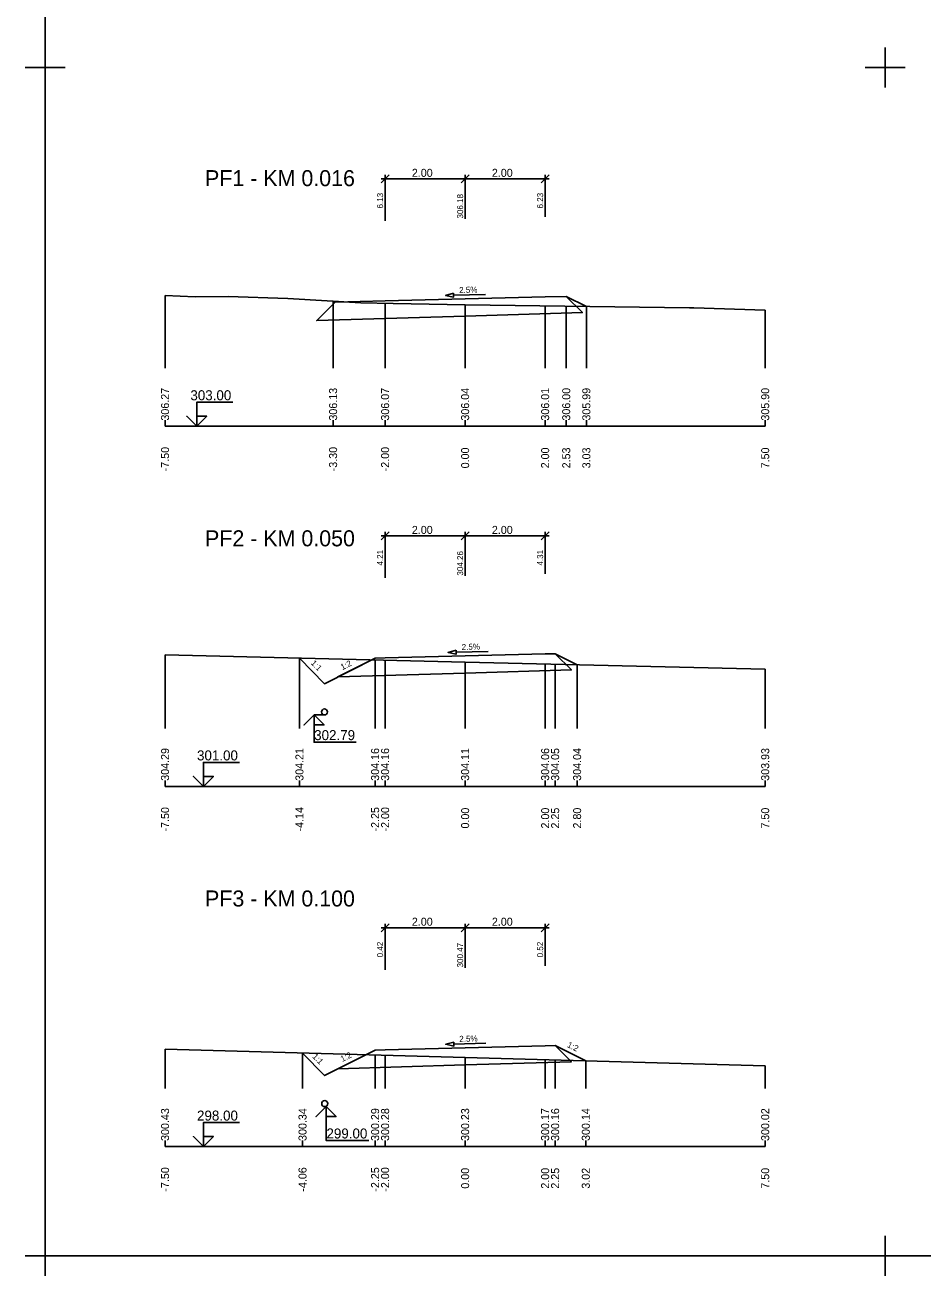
# Model space of a CAD drawing. Extents: x -5 to 1895, y -2 to 602.
# Drawn here: x -5 to 219.4, y -2.3 to 310.3 of the extents above; entities that cross this region are included whole.
import ezdxf

# ---------------------------------------------------------------- set-up
doc = ezdxf.new("R2010")
doc.units = 0
for name, color, linetype in [('KOTA', 7, 'Continuous'), ('KOTA_DELKY', 7, 'Continuous'), ('KOTA_DELKY_CONT', 7, 'Continuous'), ('KRIZENI', 7, 'Continuous'), ('NS_TELESO_VOZOVKY', 7, 'Continuous'), ('NS_V_PF', 7, 'Continuous'), ('REZY_PF_PUVODNI', 7, 'Continuous'), ('SESTAVY_REZU_PF', 7, 'Continuous'), ('SKLON', 7, 'Continuous'), ('SVK', 7, 'Continuous')]:
    doc.layers.add(name, color=color, linetype=linetype)

msp = doc.modelspace()

# ---------------------------------------------------------------- linework, layer by layer
for p, q in [((0, 304.67), (0, 294.67)), ((0, 304.67), (0, 294.67)), ((0, 304.67), (0, 294.67)), ((0, 304.67), (0, 294.67)), ((0, 304.67), (0, 294.67)), ((0, 304.67), (0, 294.67)), ((0, 304.67), (0, 294.67)), ((0, 304.67), (0, 294.67)), ((0, 304.67), (0, 294.67)), ((0, 304.67), (0, 294.67)), ((0, 304.67), (0, 294.67)), ((0, 304.67), (0, 294.67)), ((0, 304.67), (0, 294.67)), ((0, 304.67), (0, 294.67)), ((0, 304.67), (0, 294.67)), ((0, 304.67), (0, 294.67)), ((0, 304.67), (0, 294.67)), ((0, 304.67), (0, 294.67)), ((0, 304.67), (0, 294.67)), ((0, 304.67), (0, 294.67)), ((0, 304.67), (0, 294.67)), ((0, 304.67), (0, 294.67)), ((0, 304.67), (0, 294.67)), ((0, 304.67), (0, 294.67)), ((0, 304.67), (0, 294.67)), ((0, 304.67), (0, 294.67)), ((0, 304.67), (0, 294.67)), ((0, 304.67), (0, 294.67)), ((0, 304.67), (0, 294.67)), ((0, 304.67), (0, 294.67)), ((0, 304.67), (0, 294.67)), ((0, 304.67), (0, 294.67)), ((0, 304.67), (0, 294.67)), ((0, 304.67), (0, 294.67)), ((0, 304.67), (0, 294.67)), ((0, 304.67), (0, 294.67)), ((210, 304.67), (210, 294.67)), ((210, 304.67), (210, 294.67)), ((210, 304.67), (210, 294.67)), ((210, 304.67), (210, 294.67)), ((210, 304.67), (210, 294.67)), ((210, 304.67), (210, 294.67)), ((210, 304.67), (210, 294.67)), ((210, 304.67), (210, 294.67)), ((210, 304.67), (210, 294.67)), ((210, 304.67), (210, 294.67)), ((210, 304.67), (210, 294.67)), ((210, 304.67), (210, 294.67)), ((210, 304.67), (210, 294.67)), ((210, 304.67), (210, 294.67)), ((210, 304.67), (210, 294.67)), ((210, 304.67), (210, 294.67)), ((210, 304.67), (210, 294.67)), ((210, 304.67), (210, 294.67)), ((210, 304.67), (210, 294.67)), ((210, 304.67), (210, 294.67)), ((210, 304.67), (210, 294.67)), ((210, 304.67), (210, 294.67)), ((210, 304.67), (210, 294.67)), ((210, 304.67), (210, 294.67)), ((210, 304.67), (210, 294.67)), ((210, 304.67), (210, 294.67)), ((210, 304.67), (210, 294.67)), ((210, 304.67), (210, 294.67)), ((210, 304.67), (210, 294.67)), ((210, 304.67), (210, 294.67)), ((210, 304.67), (210, 294.67)), ((210, 304.67), (210, 294.67)), ((210, 304.67), (210, 294.67)), ((210, 304.67), (210, 294.67)), ((210, 304.67), (210, 294.67)), ((210, 304.67), (210, 294.67)), ((210, 304.67), (210, 294.67)), ((210, 304.67), (210, 294.67)), ((210, 304.67), (210, 294.67)), ((210, 304.67), (210, 294.67)), ((210, 304.67), (210, 294.67)), ((210, 304.67), (210, 294.67)), ((210, 304.67), (210, 294.67)), ((210, 304.67), (210, 294.67)), ((210, 304.67), (210, 294.67)), ((210, 304.67), (210, 294.67)), ((210, 304.67), (210, 294.67)), ((210, 304.67), (210, 294.67)), ((210, 304.67), (210, 294.67)), ((210, 304.67), (210, 294.67)), ((210, 304.67), (210, 294.67)), ((210, 304.67), (210, 294.67)), ((210, 304.67), (210, 294.67)), ((210, 304.67), (210, 294.67)), ((5, 299.67), (-5, 299.67)), ((5, 299.67), (-5, 299.67)), ((5, 299.67), (-5, 299.67)), ((5, 299.67), (-5, 299.67)), ((5, 299.67), (-5, 299.67)), ((5, 299.67), (-5, 299.67)), ((5, 299.67), (-5, 299.67)), ((5, 299.67), (-5, 299.67)), ((5, 299.67), (-5, 299.67)), ((5, 299.67), (-5, 299.67)), ((5, 299.67), (-5, 299.67)), ((5, 299.67), (-5, 299.67)), ((5, 299.67), (-5, 299.67)), ((5, 299.67), (-5, 299.67)), ((5, 299.67), (-5, 299.67)), ((5, 299.67), (-5, 299.67)), ((5, 299.67), (-5, 299.67)), ((5, 299.67), (-5, 299.67)), ((5, 299.67), (-5, 299.67)), ((5, 299.67), (-5, 299.67)), ((5, 299.67), (-5, 299.67)), ((5, 299.67), (-5, 299.67)), ((5, 299.67), (-5, 299.67)), ((5, 299.67), (-5, 299.67)), ((5, 299.67), (-5, 299.67)), ((5, 299.67), (-5, 299.67)), ((5, 299.67), (-5, 299.67)), ((5, 299.67), (-5, 299.67)), ((5, 299.67), (-5, 299.67)), ((5, 299.67), (-5, 299.67)), ((5, 299.67), (-5, 299.67)), ((5, 299.67), (-5, 299.67)), ((5, 299.67), (-5, 299.67)), ((5, 299.67), (-5, 299.67)), ((5, 299.67), (-5, 299.67)), ((5, 299.67), (-5, 299.67)), ((215, 299.67), (205, 299.67)), ((215, 299.67), (205, 299.67)), ((215, 299.67), (205, 299.67)), ((215, 299.67), (205, 299.67)), ((215, 299.67), (205, 299.67)), ((215, 299.67), (205, 299.67)), ((215, 299.67), (205, 299.67)), ((215, 299.67), (205, 299.67)), ((215, 299.67), (205, 299.67)), ((215, 299.67), (205, 299.67)), ((215, 299.67), (205, 299.67)), ((215, 299.67), (205, 299.67)), ((215, 299.67), (205, 299.67)), ((215, 299.67), (205, 299.67)), ((215, 299.67), (205, 299.67)), ((215, 299.67), (205, 299.67)), ((215, 299.67), (205, 299.67)), ((215, 299.67), (205, 299.67)), ((215, 299.67), (205, 299.67)), ((215, 299.67), (205, 299.67)), ((215, 299.67), (205, 299.67)), ((215, 299.67), (205, 299.67)), ((215, 299.67), (205, 299.67)), ((215, 299.67), (205, 299.67)), ((215, 299.67), (205, 299.67)), ((215, 299.67), (205, 299.67)), ((215, 299.67), (205, 299.67)), ((215, 299.67), (205, 299.67)), ((215, 299.67), (205, 299.67)), ((215, 299.67), (205, 299.67)), ((215, 299.67), (205, 299.67)), ((215, 299.67), (205, 299.67)), ((215, 299.67), (205, 299.67)), ((215, 299.67), (205, 299.67)), ((215, 299.67), (205, 299.67)), ((215, 299.67), (205, 299.67)), ((215, 299.67), (205, 299.67)), ((215, 299.67), (205, 299.67)), ((215, 299.67), (205, 299.67)), ((215, 299.67), (205, 299.67)), ((215, 299.67), (205, 299.67)), ((215, 299.67), (205, 299.67)), ((215, 299.67), (205, 299.67)), ((215, 299.67), (205, 299.67)), ((215, 299.67), (205, 299.67)), ((215, 299.67), (205, 299.67)), ((215, 299.67), (205, 299.67)), ((215, 299.67), (205, 299.67)), ((215, 299.67), (205, 299.67)), ((215, 299.67), (205, 299.67)), ((215, 299.67), (205, 299.67)), ((215, 299.67), (205, 299.67)), ((215, 299.67), (205, 299.67)), ((215, 299.67), (205, 299.67)), ((0, 7.67), (0, -2.33)), ((0, 7.67), (0, -2.33)), ((0, 7.67), (0, -2.33)), ((0, 7.67), (0, -2.33)), ((0, 7.67), (0, -2.33)), ((0, 7.67), (0, -2.33)), ((0, 7.67), (0, -2.33)), ((0, 7.67), (0, -2.33)), ((210, 7.67), (210, -2.33)), ((210, 7.67), (210, -2.33)), ((210, 7.67), (210, -2.33)), ((210, 7.67), (210, -2.33)), ((210, 7.67), (210, -2.33)), ((210, 7.67), (210, -2.33)), ((210, 7.67), (210, -2.33)), ((210, 7.67), (210, -2.33)), ((210, 7.67), (210, -2.33)), ((210, 7.67), (210, -2.33)), ((210, 7.67), (210, -2.33)), ((210, 7.67), (210, -2.33)), ((5, 2.67), (-5, 2.67)), ((5, 2.67), (-5, 2.67)), ((5, 2.67), (-5, 2.67)), ((5, 2.67), (-5, 2.67)), ((5, 2.67), (-5, 2.67)), ((5, 2.67), (-5, 2.67)), ((5, 2.67), (-5, 2.67)), ((5, 2.67), (-5, 2.67)), ((215, 2.67), (205, 2.67)), ((215, 2.67), (205, 2.67)), ((215, 2.67), (205, 2.67)), ((215, 2.67), (205, 2.67)), ((215, 2.67), (205, 2.67)), ((215, 2.67), (205, 2.67)), ((215, 2.67), (205, 2.67)), ((215, 2.67), (205, 2.67)), ((215, 2.67), (205, 2.67)), ((215, 2.67), (205, 2.67)), ((215, 2.67), (205, 2.67)), ((215, 2.67), (205, 2.67))]:
    msp.add_line(p, q)
msp.add_lwpolyline([(0, 596.67), (1890, 596.67), (1890, 2.67), (0, 2.67)], close=True)
at = {"layer": 'KOTA'}
for points in [[(37.91, 210), (35.41, 212.5), (37.91, 210), (37.91, 216), (46.91, 216)], [(37.91, 210), (40.41, 212.5), (37.91, 212.5), (37.91, 210)], [(37.91, 210), (40.41, 212.5), (37.91, 212.5)], [(67.25, 137.86), (64.75, 135.36), (67.25, 137.86), (67.25, 131.04), (77.79, 131.04)], [(69.85, 137.86), (67.25, 137.86)], [(67.25, 137.86), (69.75, 135.36), (67.25, 135.36), (67.25, 137.86)], [(67.25, 137.86), (69.75, 135.36), (67.25, 135.36)], [(39.57, 120), (37.07, 122.5), (39.57, 120), (39.57, 126), (48.57, 126)], [(39.57, 120), (42.07, 122.5), (39.57, 122.5), (39.57, 120)], [(39.57, 120), (42.07, 122.5), (39.57, 122.5)], [(70.25, 39.98), (67.75, 37.48), (70.25, 39.98), (70.25, 31.53), (80.93, 31.53)], [(69.91, 39.98), (70.25, 39.98)], [(70.25, 39.98), (72.75, 37.48), (70.25, 37.48), (70.25, 39.98)], [(70.25, 39.98), (72.75, 37.48), (70.25, 37.48)], [(39.57, 30), (37.07, 32.5), (39.57, 30), (39.57, 36), (48.57, 36)], [(39.57, 30), (42.07, 32.5), (39.57, 32.5), (39.57, 30)], [(39.57, 30), (42.07, 32.5), (39.57, 32.5)]]:
    msp.add_lwpolyline(points, dxfattribs=at)
at = {"layer": 'KOTA_DELKY'}
for points in [[(84, 270.83), (86, 272.83)], [(85, 261.33), (85, 272.83)], [(104, 270.83), (106, 272.83)], [(104, 270.83), (106, 272.83)], [(105, 261.83), (105, 272.83)], [(105, 261.83), (105, 272.83)], [(124, 270.83), (126, 272.83)], [(125, 262.33), (125, 272.83)], [(84, 271.83), (106, 271.83)], [(104, 271.83), (126, 271.83)], [(84, 181.6), (86, 183.6)], [(84, 182.6), (106, 182.6)], [(85, 172.1), (85, 183.6)], [(104, 181.6), (106, 183.6)], [(104, 181.6), (106, 183.6)], [(104, 182.6), (126, 182.6)], [(105, 172.6), (105, 183.6)], [(105, 172.6), (105, 183.6)], [(124, 181.6), (126, 183.6)], [(125, 173.1), (125, 183.6)], [(84, 83.69), (86, 85.69)], [(84, 83.69), (86, 85.69)], [(84, 84.69), (106, 84.69)], [(84, 84.69), (106, 84.69)], [(85, 74.19), (85, 85.69)], [(85, 74.19), (85, 85.69)], [(104, 83.69), (106, 85.69)], [(104, 83.69), (106, 85.69)], [(104, 83.69), (106, 85.69)], [(104, 83.69), (106, 85.69)], [(104, 84.69), (126, 84.69)], [(104, 84.69), (126, 84.69)], [(105, 74.69), (105, 85.69)], [(105, 74.69), (105, 85.69)], [(105, 74.69), (105, 85.69)], [(105, 74.69), (105, 85.69)], [(124, 83.69), (126, 85.69)], [(124, 83.69), (126, 85.69)], [(125, 75.19), (125, 85.69)], [(125, 75.19), (125, 85.69)]]:
    msp.add_lwpolyline(points, dxfattribs=at)
at = {"layer": 'KRIZENI'}
for centre in [(69.85, 138.61), (69.91, 40.73)]:
    msp.add_circle(centre, 0.75, dxfattribs=at)
at = {"layer": 'NS_TELESO_VOZOVKY'}
for points in [[(105, 241.83), (125, 242.33), (130.27, 242.46), (134.33, 238.41), (105, 237.53), (67.9, 236.42), (72.5, 241.02), (85, 241.33), (105, 241.83)], [(105, 152.6), (125, 153.1), (127.5, 153.16), (131.57, 149.1), (105, 148.3), (73.2, 147.35), (82.5, 152.04), (85, 152.1), (105, 152.6)], [(105, 54.69), (125, 55.19), (127.5, 55.25), (131.57, 51.19), (105, 50.39), (73.2, 49.44), (82.5, 54.13), (85, 54.19), (105, 54.69)], [(105, 54.69), (125, 55.19), (127.5, 55.25), (131.57, 51.19), (105, 50.39), (73.2, 49.44), (82.5, 54.13), (85, 54.19), (105, 54.69)]]:
    msp.add_lwpolyline(points, dxfattribs=at)
at = {"layer": 'NS_V_PF'}
for points in [[(72, 241.27), (72.5, 241.02), (85, 241.33), (105, 241.83), (125, 242.33), (130.27, 242.46), (135.3, 239.95)], [(63.59, 152.07), (69.87, 145.66), (82.5, 152.04), (85, 152.1), (105, 152.6), (125, 153.1), (127.5, 153.16), (132.99, 150.41)], [(64.36, 53.38), (69.87, 47.76), (82.5, 54.13), (85, 54.19), (105, 54.69), (125, 55.19), (127.5, 55.25), (135.16, 51.42)], [(64.36, 53.38), (69.87, 47.76), (82.5, 54.13), (85, 54.19), (105, 54.69), (125, 55.19), (127.5, 55.25), (135.16, 51.42)]]:
    msp.add_lwpolyline(points, dxfattribs=at)
at = {"layer": 'REZY_PF_PUVODNI'}
for points in [[(30, 242.68), (37.51, 242.32), (45.81, 242.45), (60.66, 241.93), (78.9, 240.87), (87, 240.64), (105, 240.38), (161.04, 239.58), (162.2, 239.58), (180, 239.02)], [(30, 152.87), (105, 151.08), (105, 151.08), (180, 149.29)], [(30, 54.33), (105, 52.26), (105, 52.26), (180, 50.19)]]:
    msp.add_lwpolyline(points, dxfattribs=at)
at = {"layer": 'SESTAVY_REZU_PF'}
for points in [[(30, 210), (180, 210)], [(30, 120), (180, 120)], [(30, 30), (180, 30)]]:
    msp.add_lwpolyline(points, dxfattribs=at)
at = {"layer": 'SKLON'}
for points in [[(102.11, 243.26), (100.12, 242.71), (102.13, 242.26), (102.11, 243.26)], [(102.12, 242.76), (110.12, 242.96)], [(102.74, 154.04), (100.75, 153.49), (102.76, 153.04), (102.74, 154.04)], [(102.75, 153.54), (110.75, 153.74)], [(102.15, 56.12), (100.17, 55.57), (102.18, 55.12), (102.15, 56.12)], [(102.17, 55.62), (110.16, 55.82)]]:
    msp.add_lwpolyline(points, dxfattribs=at)
for points in [[(102.11, 243.26), (100.12, 242.71), (102.13, 242.26)], [(102.74, 154.04), (100.75, 153.49), (102.76, 153.04)], [(102.15, 56.12), (100.17, 55.57), (102.18, 55.12)]]:
    msp.add_lwpolyline(points, close=True, dxfattribs=at)
at = {"layer": 'SVK'}
for points in [[(30, 224.5), (30, 242.68)], [(72, 224.5), (72, 241.27)], [(85, 224.5), (85, 240.69)], [(105, 224.5), (105, 240.38)], [(125, 224.5), (125, 240.09)], [(130.27, 224.5), (130.27, 240.02)], [(135.3, 224.5), (135.3, 239.95)], [(180, 224.5), (180, 239.02)], [(30, 210), (30, 211.5)], [(72, 210), (72, 211.5)], [(85, 210), (85, 211.5)], [(105, 210), (105, 211.5)], [(125, 210), (125, 211.5)], [(130.27, 210), (130.27, 211.5)], [(135.3, 210), (135.3, 211.5)], [(180, 210), (180, 211.5)], [(30, 134.5), (30, 152.87)], [(63.59, 134.5), (63.59, 152.07)], [(82.5, 134.5), (82.5, 151.62)], [(85, 134.5), (85, 151.56)], [(105, 134.5), (105, 151.08)], [(125, 134.5), (125, 150.6)], [(127.5, 134.5), (127.5, 150.55)], [(132.99, 134.5), (132.99, 150.41)], [(180, 134.5), (180, 149.29)], [(30, 120), (30, 121.5)], [(63.59, 120), (63.59, 121.5)], [(82.5, 120), (82.5, 121.5)], [(85, 120), (85, 121.5)], [(105, 120), (105, 121.5)], [(125, 120), (125, 121.5)], [(127.5, 120), (127.5, 121.5)], [(132.99, 120), (132.99, 121.5)], [(180, 120), (180, 121.5)], [(30, 44.5), (30, 54.33)], [(64.36, 44.5), (64.36, 53.38)], [(82.5, 44.5), (82.5, 52.88)], [(85, 44.5), (85, 52.81)], [(105, 44.5), (105, 52.26)], [(125, 44.5), (125, 51.7)], [(127.5, 44.5), (127.5, 51.64)], [(135.16, 44.5), (135.16, 51.42)], [(180, 44.5), (180, 50.19)], [(30, 30), (30, 31.5)], [(64.36, 30), (64.36, 31.5)], [(82.5, 30), (82.5, 31.5)], [(85, 30), (85, 31.5)], [(105, 30), (105, 31.5)], [(125, 30), (125, 31.5)], [(127.5, 30), (127.5, 31.5)], [(135.16, 30), (135.16, 31.5)], [(180, 30), (180, 31.5)]]:
    msp.add_lwpolyline(points, dxfattribs=at)

# ---------------------------------------------------------------- texts
at = {"layer": 'KOTA'}
for s, p in [('303.00', (36.33, 216.5)), ('302.79', (67.27, 131.57)), ('301.00', (37.99, 126.5)), ('298.00', (37.99, 36.5)), ('299.00', (70.34, 32.03))]:
    msp.add_text(s, height=2.5, dxfattribs=at).set_placement(p)
at = {"layer": 'KOTA_DELKY'}
for p in [(91.69, 272.33), (111.69, 272.33), (91.69, 183.1), (111.69, 183.1), (91.69, 85.19), (91.69, 85.19), (111.69, 85.19), (111.69, 85.19)]:
    msp.add_text('2.00', height=2, dxfattribs=at).set_placement(p)
at = {"layer": 'KOTA_DELKY_CONT'}
for s, p in [('6.13', (84.5, 264.42)), ('306.18', (104.5, 261.91)), ('6.23', (124.5, 264.42)), ('4.21', (84.5, 175.19)), ('304.26', (104.5, 172.68)), ('4.31', (124.5, 175.19)), ('0.42', (84.5, 77.28)), ('0.42', (84.5, 77.28)), ('300.47', (104.5, 74.77)), ('300.47', (104.5, 74.77)), ('0.52', (124.5, 77.28)), ('0.52', (124.5, 77.28))]:
    msp.add_text(s, height=1.5, rotation=90, dxfattribs=at).set_placement(p)
at = {"layer": 'SESTAVY_REZU_PF'}
for s, p in [('PF1 - KM 0.016', (40, 270)), ('PF2 - KM 0.050', (40, 180)), ('PF3 - KM 0.100', (40, 90))]:
    msp.add_text(s, height=4, dxfattribs=at).set_placement(p)
at = {"layer": 'SKLON'}
for s, rotation, p in [('2.5%', 1.4321, (103.52, 243.29)), ('2.5%', 1.4321, (104.15, 154.08)), ('1:1', 314.4213, (66.34, 150.69)), ('1:2', 26.7649, (74.32, 149.03)), ('2.5%', 1.4321, (103.56, 56.16)), ('1:2', 26.7649, (74.32, 51.13)), ('1:2', 26.7649, (74.32, 51.13)), ('1:2', 333.4349, (130.37, 54.94)), ('1:1', 314.4213, (66.72, 52.39))]:
    msp.add_text(s, height=1.5, rotation=rotation, dxfattribs=at).set_placement(p)
at = {"layer": 'SVK'}
for s, p in [(' 306.27', (31, 210.67)), (' 306.13', (73, 210.67)), (' 306.07', (86, 210.67)), (' 306.04', (106, 210.67)), (' 306.01', (126, 210.67)), (' 306.00', (131.27, 210.67)), (' 305.99', (136.3, 210.67)), (' 305.90', (181, 210.67)), (' -7.50', (31, 198)), (' -3.30', (73, 198)), (' -2.00', (86, 198)), ('  0.00', (106, 198)), ('  2.00', (126, 198)), ('  2.53', (131.27, 198)), ('  3.03', (136.3, 198)), ('  7.50', (181, 198)), (' 304.29', (31, 120.67)), (' 304.21', (64.59, 120.67)), (' 304.16', (83.5, 120.67)), (' 304.16', (86, 120.67)), (' 304.11', (106, 120.67)), (' 304.06', (126, 120.67)), (' 304.05', (128.5, 120.67)), (' 304.04', (133.99, 120.67)), (' 303.93', (181, 120.67)), (' -7.50', (31, 108)), (' -4.14', (64.59, 108)), (' -2.25', (83.5, 108)), (' -2.00', (86, 108)), ('  0.00', (106, 108)), ('  2.00', (126, 108)), ('  2.25', (128.5, 108)), ('  2.80', (133.99, 108)), ('  7.50', (181, 108)), (' 300.43', (31, 30.67)), (' 300.34', (65.36, 30.67)), (' 300.29', (83.5, 30.67)), (' 300.28', (86, 30.67)), (' 300.23', (106, 30.67)), (' 300.17', (126, 30.67)), (' 300.16', (128.5, 30.67)), (' 300.14', (136.16, 30.67)), (' 300.02', (181, 30.67)), (' -7.50', (31, 18)), (' -4.06', (65.36, 18)), (' -2.25', (83.5, 18)), (' -2.00', (86, 18)), ('  0.00', (106, 18)), ('  2.00', (126, 18)), ('  2.25', (128.5, 18)), ('  3.02', (136.16, 18)), ('  7.50', (181, 18))]:
    msp.add_text(s, height=2, rotation=90, dxfattribs=at).set_placement(p)

doc.saveas('drawing.dxf')
